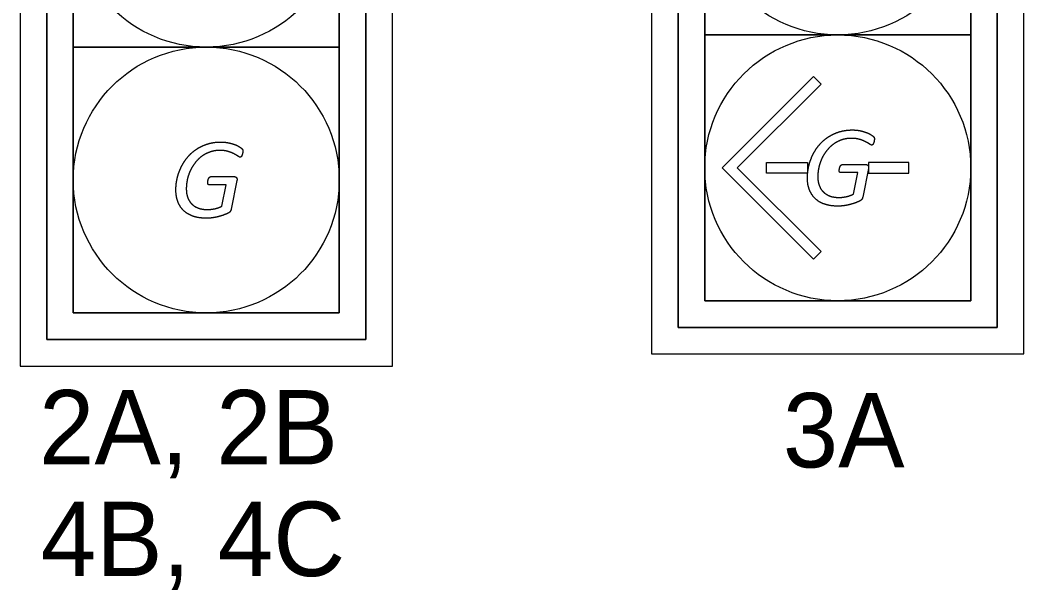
# Model space of a CAD drawing. Extents: x 0 to 34, y 0 to 22.
# Drawn here: x 20.763 to 22.65, y 18.427 to 19.499 of the extents above; entities that cross this region are included whole.
import ezdxf

# ---------------------------------------------------------------- set-up
doc = ezdxf.new("R2010")
doc.units = 0
doc.layers.add('SC_Scratch1', color=7, linetype='Continuous')
doc.layers.add('UT_X_Electric', color=7, linetype='Continuous')

msp = doc.modelspace()

# ---------------------------------------------------------------- linework, layer by layer
at = {"layer": 'SC_Scratch1'}
for p, q in [((22.0828, 19.2208), (22.2546, 19.3925)), ((22.2546, 19.3925), (22.2687, 19.3784)), ((22.2687, 19.3784), (22.1111, 19.2208)), ((22.2546, 19.0491), (22.0828, 19.2208)), ((22.1111, 19.2208), (22.2687, 19.0632)), ((22.3085, 19.227), (22.3528, 19.227)), ((22.3085, 19.227), (22.3528, 19.227)), ((22.3578, 19.2195), (22.347, 19.1658)), ((22.3578, 19.2195), (22.347, 19.1658)), ((21.1212, 19.2043), (21.1655, 19.2043)), ((21.1212, 19.2043), (21.1655, 19.2043)), ((21.1705, 19.1968), (21.1597, 19.1431)), ((21.1705, 19.1968), (21.1597, 19.1431)), ((22.2687, 19.0632), (22.2546, 19.0491))]:
    msp.add_line(p, q, dxfattribs=at)
for points in [[(22.6501, 18.8708), (22.6501, 20.0708), (22.6501, 20.0708), (22.6501, 20.5708), (21.9501, 20.5708), (21.9501, 20.0708), (21.9501, 20.0708), (21.9501, 18.8708)], [(20.7628, 18.848), (21.4628, 18.848), (21.4628, 20.548), (20.7628, 20.548)], [(22.0001, 18.9208), (22.0001, 20.0208), (22.0001, 20.0208), (22.0001, 20.5208), (22.6001, 20.5208), (22.6001, 20.0208), (22.6001, 20.0208), (22.6001, 18.9208)], [(22.6001, 18.9208), (22.6001, 20.0208), (22.6001, 20.0208), (22.6001, 20.5208), (22.0001, 20.5208), (22.0001, 20.0208), (22.0001, 20.0208), (22.0001, 18.9208)], [(20.8128, 20.498), (21.4128, 20.498), (21.4128, 18.898), (20.8128, 18.898)], [(20.8128, 18.898), (21.4128, 18.898), (21.4128, 20.498), (20.8128, 20.498)], [(22.0501, 18.9708), (22.0501, 19.9708), (22.0501, 19.9708), (22.0501, 20.4708), (22.5501, 20.4708), (22.5501, 19.9708), (22.5501, 19.9708), (22.5501, 18.9708)], [(20.8628, 20.448), (21.3628, 20.448), (21.3628, 18.948), (20.8628, 18.948)], [(22.0501, 19.4708), (22.5501, 19.4708), (22.5501, 19.9708), (22.0501, 19.9708)], [(20.8628, 19.448), (21.3628, 19.448), (21.3628, 19.948), (20.8628, 19.948)], [(22.0501, 19.4708), (22.0501, 18.9708), (22.5501, 18.9708), (22.5501, 19.4708)], [(20.8628, 18.948), (21.3628, 18.948), (21.3628, 19.448), (20.8628, 19.448)], [(22.1662, 19.2108), (22.1662, 19.2308), (22.2433, 19.2308), (22.2433, 19.2108)], [(22.434, 19.2108), (22.434, 19.2308), (22.358, 19.2308), (22.358, 19.2108)]]:
    msp.add_lwpolyline(points, close=True, dxfattribs=at)
for points in [[(22.3297, 19.1714), (22.3377, 19.2118), (22.3055, 19.2118)], [(22.3297, 19.1714), (22.3377, 19.2118), (22.3055, 19.2118)], [(21.1423, 19.1487), (21.1504, 19.189), (21.1182, 19.189)], [(21.1423, 19.1487), (21.1504, 19.189), (21.1182, 19.189)]]:
    msp.add_lwpolyline(points, dxfattribs=at)
for centre in [(22.3001, 19.7208), (21.1128, 19.698), (22.3001, 19.2208), (21.1128, 19.198)]:
    msp.add_circle(centre, 0.25, dxfattribs=at)
for points in [[(22.3029, 19.2885), (22.3143, 19.2921), (22.3274, 19.2921)], [(22.3029, 19.2885), (22.3143, 19.2921), (22.3274, 19.2921)], [(22.3274, 19.2921), (22.3349, 19.2921), (22.3415, 19.2908)], [(22.3274, 19.2921), (22.3349, 19.2921), (22.3415, 19.2908)], [(22.3415, 19.2908), (22.3481, 19.2894), (22.3532, 19.2875)], [(22.3415, 19.2908), (22.3481, 19.2894), (22.3532, 19.2875)], [(22.2655, 19.2642), (22.2728, 19.2727), (22.2822, 19.2788)], [(22.2655, 19.2642), (22.2728, 19.2727), (22.2822, 19.2788)], [(22.2822, 19.2788), (22.2916, 19.285), (22.3029, 19.2885)], [(22.2822, 19.2788), (22.2916, 19.285), (22.3029, 19.2885)], [(22.3076, 19.2735), (22.2993, 19.2706), (22.2923, 19.2656)], [(22.3076, 19.2735), (22.2993, 19.2706), (22.2923, 19.2656)], [(22.3256, 19.2763), (22.316, 19.2763), (22.3076, 19.2735)], [(22.3256, 19.2763), (22.316, 19.2763), (22.3076, 19.2735)], [(22.3413, 19.2743), (22.3347, 19.2763), (22.3256, 19.2763)], [(22.3413, 19.2743), (22.3347, 19.2763), (22.3256, 19.2763)], [(22.3524, 19.2699), (22.3479, 19.2723), (22.3413, 19.2743)], [(22.3524, 19.2699), (22.3479, 19.2723), (22.3413, 19.2743)], [(22.3598, 19.2655), (22.357, 19.2675), (22.3524, 19.2699)], [(22.3598, 19.2655), (22.357, 19.2675), (22.3524, 19.2699)], [(22.3532, 19.2875), (22.3584, 19.2856), (22.362, 19.2834)], [(22.3532, 19.2875), (22.3584, 19.2856), (22.362, 19.2834)], [(22.362, 19.2834), (22.3655, 19.2811), (22.3668, 19.28)], [(22.362, 19.2834), (22.3655, 19.2811), (22.3668, 19.28)], [(22.3668, 19.28), (22.3681, 19.2788), (22.3685, 19.2777)], [(22.3668, 19.28), (22.3681, 19.2788), (22.3685, 19.2777)], [(22.3684, 19.2707), (22.3681, 19.2695), (22.3677, 19.2681)], [(22.3684, 19.2707), (22.3681, 19.2695), (22.3677, 19.2681)], [(22.3688, 19.2731), (22.3686, 19.272), (22.3684, 19.2707)], [(22.3688, 19.2731), (22.3686, 19.272), (22.3684, 19.2707)], [(22.3685, 19.2777), (22.369, 19.2766), (22.369, 19.275)], [(22.3685, 19.2777), (22.369, 19.2766), (22.369, 19.275)], [(22.369, 19.275), (22.369, 19.2742), (22.3688, 19.2731)], [(22.369, 19.275), (22.369, 19.2742), (22.3688, 19.2731)], [(21.0782, 19.2415), (21.0854, 19.25), (21.0949, 19.2561)], [(21.0782, 19.2415), (21.0854, 19.25), (21.0949, 19.2561)], [(21.0949, 19.2561), (21.1043, 19.2623), (21.1156, 19.2658)], [(21.0949, 19.2561), (21.1043, 19.2623), (21.1156, 19.2658)], [(21.1156, 19.2658), (21.1269, 19.2694), (21.1401, 19.2694)], [(21.1156, 19.2658), (21.1269, 19.2694), (21.1401, 19.2694)], [(21.1382, 19.2536), (21.1286, 19.2536), (21.1203, 19.2507)], [(21.1382, 19.2536), (21.1286, 19.2536), (21.1203, 19.2507)], [(21.154, 19.2516), (21.1474, 19.2536), (21.1382, 19.2536)], [(21.154, 19.2516), (21.1474, 19.2536), (21.1382, 19.2536)], [(21.1401, 19.2694), (21.1476, 19.2694), (21.1542, 19.268)], [(21.1401, 19.2694), (21.1476, 19.2694), (21.1542, 19.268)], [(21.1651, 19.2472), (21.1605, 19.2496), (21.154, 19.2516)], [(21.1651, 19.2472), (21.1605, 19.2496), (21.154, 19.2516)], [(21.1542, 19.268), (21.1607, 19.2667), (21.1659, 19.2648)], [(21.1542, 19.268), (21.1607, 19.2667), (21.1659, 19.2648)], [(21.1659, 19.2648), (21.1711, 19.2629), (21.1746, 19.2607)], [(21.1659, 19.2648), (21.1711, 19.2629), (21.1746, 19.2607)], [(21.1746, 19.2607), (21.1782, 19.2584), (21.1795, 19.2572)], [(21.1746, 19.2607), (21.1782, 19.2584), (21.1795, 19.2572)], [(21.1795, 19.2572), (21.1808, 19.256), (21.1812, 19.255)], [(21.1795, 19.2572), (21.1808, 19.256), (21.1812, 19.255)], [(21.1812, 19.255), (21.1816, 19.2539), (21.1816, 19.2523)], [(21.1812, 19.255), (21.1816, 19.2539), (21.1816, 19.2523)], [(21.1816, 19.2523), (21.1816, 19.2515), (21.1815, 19.2504)], [(21.1816, 19.2523), (21.1816, 19.2515), (21.1815, 19.2504)], [(22.2533, 19.2457), (22.2582, 19.2557), (22.2655, 19.2642)], [(22.2533, 19.2457), (22.2582, 19.2557), (22.2655, 19.2642)], [(22.2798, 19.2537), (22.2743, 19.2469), (22.2704, 19.2389)], [(22.2798, 19.2537), (22.2743, 19.2469), (22.2704, 19.2389)], [(22.2923, 19.2656), (22.2853, 19.2606), (22.2798, 19.2537)], [(22.2923, 19.2656), (22.2853, 19.2606), (22.2798, 19.2537)], [(22.3641, 19.2636), (22.3625, 19.2636), (22.3598, 19.2655)], [(22.3641, 19.2636), (22.3625, 19.2636), (22.3598, 19.2655)], [(22.3655, 19.2642), (22.3649, 19.2636), (22.3641, 19.2636)], [(22.3655, 19.2642), (22.3649, 19.2636), (22.3641, 19.2636)], [(22.3667, 19.2658), (22.3662, 19.2648), (22.3655, 19.2642)], [(22.3667, 19.2658), (22.3662, 19.2648), (22.3655, 19.2642)], [(22.3677, 19.2681), (22.3672, 19.2668), (22.3667, 19.2658)], [(22.3677, 19.2681), (22.3672, 19.2668), (22.3667, 19.2658)], [(21.0659, 19.2229), (21.0709, 19.2329), (21.0782, 19.2415)], [(21.0659, 19.2229), (21.0709, 19.2329), (21.0782, 19.2415)], [(21.1049, 19.2429), (21.0979, 19.2379), (21.0924, 19.231)], [(21.1049, 19.2429), (21.0979, 19.2379), (21.0924, 19.231)], [(21.1203, 19.2507), (21.1119, 19.2479), (21.1049, 19.2429)], [(21.1203, 19.2507), (21.1119, 19.2479), (21.1049, 19.2429)], [(21.1724, 19.2428), (21.1697, 19.2447), (21.1651, 19.2472)], [(21.1724, 19.2428), (21.1697, 19.2447), (21.1651, 19.2472)], [(21.1768, 19.2408), (21.1752, 19.2408), (21.1724, 19.2428)], [(21.1768, 19.2408), (21.1752, 19.2408), (21.1724, 19.2428)], [(21.1782, 19.2414), (21.1775, 19.2408), (21.1768, 19.2408)], [(21.1782, 19.2414), (21.1775, 19.2408), (21.1768, 19.2408)], [(21.1794, 19.243), (21.1788, 19.242), (21.1782, 19.2414)], [(21.1794, 19.243), (21.1788, 19.242), (21.1782, 19.2414)], [(21.1803, 19.2454), (21.1799, 19.2441), (21.1794, 19.243)], [(21.1803, 19.2454), (21.1799, 19.2441), (21.1794, 19.243)], [(21.181, 19.248), (21.1808, 19.2468), (21.1803, 19.2454)], [(21.181, 19.248), (21.1808, 19.2468), (21.1803, 19.2454)], [(21.1815, 19.2504), (21.1813, 19.2492), (21.181, 19.248)], [(21.1815, 19.2504), (21.1813, 19.2492), (21.181, 19.248)], [(22.2457, 19.2245), (22.2483, 19.2356), (22.2533, 19.2457)], [(22.2457, 19.2245), (22.2483, 19.2356), (22.2533, 19.2457)], [(22.2704, 19.2389), (22.2666, 19.2308), (22.2646, 19.222)], [(22.2704, 19.2389), (22.2666, 19.2308), (22.2646, 19.222)], [(21.0583, 19.2018), (21.061, 19.2129), (21.0659, 19.2229)], [(21.0583, 19.2018), (21.061, 19.2129), (21.0659, 19.2229)], [(21.0831, 19.2161), (21.0793, 19.2081), (21.0773, 19.1993)], [(21.0831, 19.2161), (21.0793, 19.2081), (21.0773, 19.1993)], [(21.0924, 19.231), (21.0869, 19.2242), (21.0831, 19.2161)], [(21.0924, 19.231), (21.0869, 19.2242), (21.0831, 19.2161)], [(22.243, 19.2018), (22.243, 19.2133), (22.2457, 19.2245)], [(22.243, 19.2018), (22.243, 19.2133), (22.2457, 19.2245)], [(22.2646, 19.222), (22.2626, 19.2132), (22.2626, 19.2041)], [(22.2646, 19.222), (22.2626, 19.2132), (22.2626, 19.2041)], [(22.3029, 19.2153), (22.3029, 19.2161), (22.303, 19.2173)], [(22.3029, 19.2153), (22.3029, 19.2161), (22.303, 19.2173)], [(22.3036, 19.2127), (22.3029, 19.2136), (22.3029, 19.2153)], [(22.3036, 19.2127), (22.3029, 19.2136), (22.3029, 19.2153)], [(22.303, 19.2173), (22.3032, 19.2186), (22.3034, 19.2199)], [(22.303, 19.2173), (22.3032, 19.2186), (22.3034, 19.2199)], [(22.3034, 19.2199), (22.3037, 19.2212), (22.3042, 19.2225)], [(22.3034, 19.2199), (22.3037, 19.2212), (22.3042, 19.2225)], [(22.3042, 19.2225), (22.3047, 19.2238), (22.3053, 19.2248)], [(22.3042, 19.2225), (22.3047, 19.2238), (22.3053, 19.2248)], [(22.3053, 19.2248), (22.306, 19.2258), (22.3068, 19.2264)], [(22.3053, 19.2248), (22.306, 19.2258), (22.3068, 19.2264)], [(22.3068, 19.2264), (22.3076, 19.227), (22.3085, 19.227)], [(22.3068, 19.2264), (22.3076, 19.227), (22.3085, 19.227)], [(22.3528, 19.227), (22.3558, 19.227), (22.3572, 19.225)], [(22.3528, 19.227), (22.3558, 19.227), (22.3572, 19.225)], [(22.3572, 19.225), (22.3585, 19.2229), (22.3578, 19.2195)], [(22.3572, 19.225), (22.3585, 19.2229), (22.3578, 19.2195)], [(21.0557, 19.1791), (21.0557, 19.1906), (21.0583, 19.2018)], [(21.0557, 19.1791), (21.0557, 19.1906), (21.0583, 19.2018)], [(21.0773, 19.1993), (21.0753, 19.1904), (21.0753, 19.1814)], [(21.0773, 19.1993), (21.0753, 19.1904), (21.0753, 19.1814)], [(21.1155, 19.1926), (21.1155, 19.1934), (21.1157, 19.1946)], [(21.1155, 19.1926), (21.1155, 19.1934), (21.1157, 19.1946)], [(21.1157, 19.1946), (21.1158, 19.1959), (21.1161, 19.1972)], [(21.1157, 19.1946), (21.1158, 19.1959), (21.1161, 19.1972)], [(21.1161, 19.1972), (21.1164, 19.1985), (21.1169, 19.1998)], [(21.1161, 19.1972), (21.1164, 19.1985), (21.1169, 19.1998)], [(21.1169, 19.1998), (21.1173, 19.201), (21.118, 19.2021)], [(21.1169, 19.1998), (21.1173, 19.201), (21.118, 19.2021)], [(21.118, 19.2021), (21.1186, 19.2031), (21.1194, 19.2037)], [(21.118, 19.2021), (21.1186, 19.2031), (21.1194, 19.2037)], [(21.1194, 19.2037), (21.1202, 19.2043), (21.1212, 19.2043)], [(21.1194, 19.2037), (21.1202, 19.2043), (21.1212, 19.2043)], [(21.1655, 19.2043), (21.1685, 19.2043), (21.1698, 19.2023)], [(21.1655, 19.2043), (21.1685, 19.2043), (21.1698, 19.2023)], [(21.1698, 19.2023), (21.1712, 19.2002), (21.1705, 19.1968)], [(21.1698, 19.2023), (21.1712, 19.2002), (21.1705, 19.1968)], [(22.2468, 19.1796), (22.243, 19.1894), (22.243, 19.2018)], [(22.2468, 19.1796), (22.243, 19.1894), (22.243, 19.2018)], [(22.2626, 19.2041), (22.2626, 19.1946), (22.2654, 19.1874)], [(22.2626, 19.2041), (22.2626, 19.1946), (22.2654, 19.1874)], [(22.3055, 19.2118), (22.3043, 19.2118), (22.3036, 19.2127)], [(22.3055, 19.2118), (22.3043, 19.2118), (22.3036, 19.2127)], [(21.0595, 19.1569), (21.0557, 19.1667), (21.0557, 19.1791)], [(21.0595, 19.1569), (21.0557, 19.1667), (21.0557, 19.1791)], [(21.0753, 19.1814), (21.0753, 19.1719), (21.078, 19.1646)], [(21.0753, 19.1814), (21.0753, 19.1719), (21.078, 19.1646)], [(21.1162, 19.19), (21.1155, 19.1909), (21.1155, 19.1926)], [(21.1162, 19.19), (21.1155, 19.1909), (21.1155, 19.1926)], [(21.1182, 19.189), (21.1169, 19.189), (21.1162, 19.19)], [(21.1182, 19.189), (21.1169, 19.189), (21.1162, 19.19)], [(22.2578, 19.1629), (22.2506, 19.1698), (22.2468, 19.1796)], [(22.2578, 19.1629), (22.2506, 19.1698), (22.2468, 19.1796)], [(22.2654, 19.1874), (22.2681, 19.1801), (22.2733, 19.1751)], [(22.2654, 19.1874), (22.2681, 19.1801), (22.2733, 19.1751)], [(21.0705, 19.1402), (21.0632, 19.1471), (21.0595, 19.1569)], [(21.0705, 19.1402), (21.0632, 19.1471), (21.0595, 19.1569)], [(21.078, 19.1646), (21.0808, 19.1574), (21.086, 19.1524)], [(21.078, 19.1646), (21.0808, 19.1574), (21.086, 19.1524)], [(22.2757, 19.1524), (22.265, 19.156), (22.2578, 19.1629)], [(22.2757, 19.1524), (22.265, 19.156), (22.2578, 19.1629)], [(22.2733, 19.1751), (22.2785, 19.1702), (22.2858, 19.1676)], [(22.2733, 19.1751), (22.2785, 19.1702), (22.2858, 19.1676)], [(22.2858, 19.1676), (22.2931, 19.1651), (22.3022, 19.1651)], [(22.2858, 19.1676), (22.2931, 19.1651), (22.3022, 19.1651)], [(22.3022, 19.1651), (22.3089, 19.1651), (22.3161, 19.1667)], [(22.3022, 19.1651), (22.3089, 19.1651), (22.3161, 19.1667)], [(22.3161, 19.1667), (22.3234, 19.1682), (22.3297, 19.1714)], [(22.3161, 19.1667), (22.3234, 19.1682), (22.3297, 19.1714)], [(22.3394, 19.1575), (22.3355, 19.1556), (22.3295, 19.1537)], [(22.3394, 19.1575), (22.3355, 19.1556), (22.3295, 19.1537)], [(22.3443, 19.1603), (22.3434, 19.1594), (22.3394, 19.1575)], [(22.3443, 19.1603), (22.3434, 19.1594), (22.3394, 19.1575)], [(22.3459, 19.1625), (22.3452, 19.1613), (22.3443, 19.1603)], [(22.3459, 19.1625), (22.3452, 19.1613), (22.3443, 19.1603)], [(22.347, 19.1658), (22.3466, 19.1638), (22.3459, 19.1625)], [(22.347, 19.1658), (22.3466, 19.1638), (22.3459, 19.1625)], [(21.0883, 19.1297), (21.0777, 19.1333), (21.0705, 19.1402)], [(21.0883, 19.1297), (21.0777, 19.1333), (21.0705, 19.1402)], [(21.086, 19.1524), (21.0911, 19.1474), (21.0985, 19.1449)], [(21.086, 19.1524), (21.0911, 19.1474), (21.0985, 19.1449)], [(21.0985, 19.1449), (21.1058, 19.1424), (21.1148, 19.1424)], [(21.0985, 19.1449), (21.1058, 19.1424), (21.1148, 19.1424)], [(21.1148, 19.1424), (21.1215, 19.1424), (21.1288, 19.1439)], [(21.1148, 19.1424), (21.1215, 19.1424), (21.1288, 19.1439)], [(21.1288, 19.1439), (21.1361, 19.1455), (21.1423, 19.1487)], [(21.1288, 19.1439), (21.1361, 19.1455), (21.1423, 19.1487)], [(21.1585, 19.1398), (21.1578, 19.1386), (21.157, 19.1376)], [(21.1585, 19.1398), (21.1578, 19.1386), (21.157, 19.1376)], [(21.1597, 19.1431), (21.1593, 19.141), (21.1585, 19.1398)], [(21.1597, 19.1431), (21.1593, 19.141), (21.1585, 19.1398)], [(22.3004, 19.1488), (22.2863, 19.1488), (22.2757, 19.1524)], [(22.3004, 19.1488), (22.2863, 19.1488), (22.2757, 19.1524)], [(22.316, 19.1503), (22.3085, 19.1488), (22.3004, 19.1488)], [(22.316, 19.1503), (22.3085, 19.1488), (22.3004, 19.1488)], [(22.3295, 19.1537), (22.3235, 19.1517), (22.316, 19.1503)], [(22.3295, 19.1537), (22.3235, 19.1517), (22.316, 19.1503)], [(21.113, 19.1261), (21.099, 19.1261), (21.0883, 19.1297)], [(21.113, 19.1261), (21.099, 19.1261), (21.0883, 19.1297)], [(21.1287, 19.1275), (21.1212, 19.1261), (21.113, 19.1261)], [(21.1287, 19.1275), (21.1212, 19.1261), (21.113, 19.1261)], [(21.1422, 19.1309), (21.1362, 19.129), (21.1287, 19.1275)], [(21.1422, 19.1309), (21.1362, 19.129), (21.1287, 19.1275)], [(21.1521, 19.1347), (21.1481, 19.1329), (21.1422, 19.1309)], [(21.1521, 19.1347), (21.1481, 19.1329), (21.1422, 19.1309)], [(21.157, 19.1376), (21.156, 19.1366), (21.1521, 19.1347)], [(21.157, 19.1376), (21.156, 19.1366), (21.1521, 19.1347)]]:
    msp.add_open_spline(points, degree=2, dxfattribs=at)

# ---------------------------------------------------------------- texts
at = {"layer": 'UT_X_Electric'}
for s, p in [('2A, 2B', (20.7984, 18.6629)), ('3A', (22.1968, 18.6573)), ('4B, 4C', (20.8016, 18.4529))]:
    msp.add_text(s, height=0.14, dxfattribs=at).set_placement(p)

doc.saveas('drawing.dxf')
